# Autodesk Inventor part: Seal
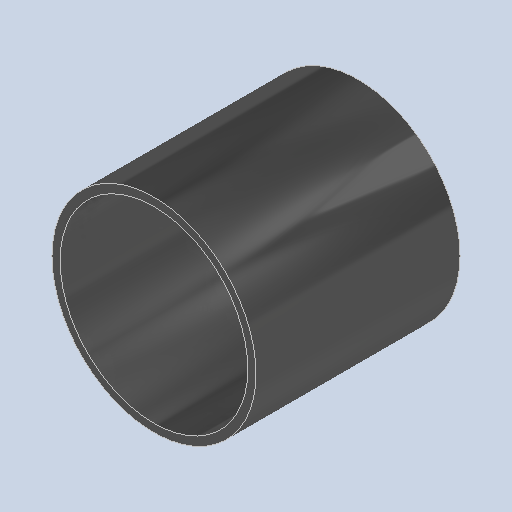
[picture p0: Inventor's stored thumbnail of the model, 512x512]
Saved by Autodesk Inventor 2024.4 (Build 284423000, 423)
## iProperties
Created: 2025-07
Part Number: Seal
Material: Generic
Document SubType Name: Modeling
Designer: AdminForWorker
Density: 1 g/cm^3
Appearance: Default
Title: Seal v1
Author: AdminForWorker
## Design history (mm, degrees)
feature "Body1"
body "Solid1"
